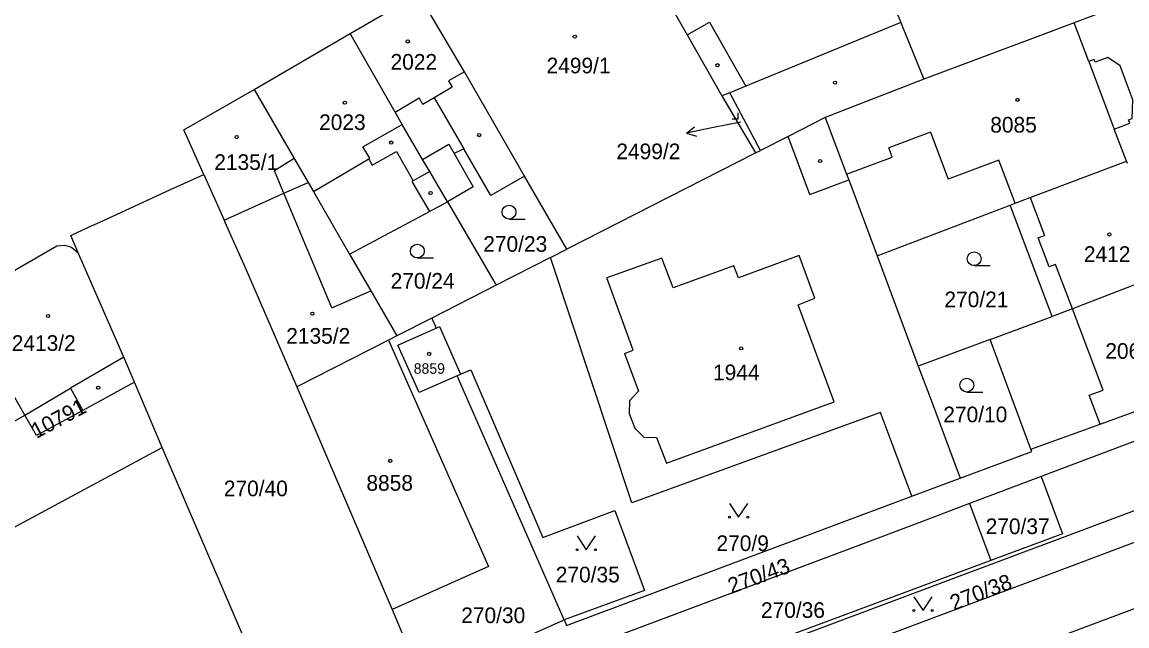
# Model space of a CAD drawing. Extents: x -564952 to -564307, y -1202373 to -1201847.
# Drawn here: x -564730.1 to -564610.1, y -1202266.1 to -1202200.5 of the extents above; entities that cross this region are included whole.
import ezdxf

# ---------------------------------------------------------------- set-up
doc = ezdxf.new("R2010")
doc.units = 0
for name, color, linetype in [('Hranice parcel', 7, 'Continuous'), ('Parcelní čísla', 7, 'Continuous'), ('Pop  PČ popisy', 7, 'Continuous'), ('Vnitřní kresba', 7, 'Continuous'), ('Značky budov', 7, 'Continuous'), ('Značky kultur', 7, 'Continuous')]:
    doc.layers.add(name, color=color, linetype=linetype)

msp = doc.modelspace()

# ---------------------------------------------------------------- linework, layer by layer
at = {"layer": 'Hranice parcel'}
for p, q in [((-564694.52, -1202201.73), (-564687.07, -1202197.41)), ((-564704.95, -1202207.82), (-564694.52, -1202201.73)), ((-564634.56, -1202200.83), (-564632.17, -1202206.71)), ((-564632.17, -1202206.71), (-564642.89, -1202210.85)), ((-564654.13, -1202208.52), (-564650.46, -1202214.71)), ((-564650.46, -1202214.71), (-564649.94, -1202214.44)), ((-564610.17, -1202215.61), (-564610.08, -1202215.84)), ((-564710.42, -1202217.06), (-564708.2, -1202222.02)), ((-564675.55, -1202217.24), (-564679.24, -1202219.35)), ((-564670.96, -1202225.17), (-564675.55, -1202217.24)), ((-564699.08, -1202217.91), (-564698.5, -1202218.91)), ((-564683.93, -1202220.03), (-564678.63, -1202229.08)), ((-564637.27, -1202225.88), (-564622.79, -1202220.37)), ((-564618.23, -1202232.47), (-564622.79, -1202220.37)), ((-564736.94, -1202230.91), (-564726.37, -1202224.82)), ((-564719.11, -1202236.91), (-564724.04, -1202225.55)), ((-564672.74, -1202226.07), (-564670.96, -1202225.17)), ((-564637.27, -1202225.88), (-564632.79, -1202237.88)), ((-564672.74, -1202226.07), (-564678.63, -1202229.08)), ((-564663.91, -1202252.75), (-564672.74, -1202226.07)), ((-564605.51, -1202227.59), (-564616.02, -1202231.64)), ((-564678.63, -1202229.08), (-564685.64, -1202232.65)), ((-564616.02, -1202231.64), (-564618.23, -1202232.47)), ((-564685.64, -1202232.65), (-564689.43, -1202234.59)), ((-564685.64, -1202232.65), (-564685.16, -1202233.75)), ((-564624.99, -1202234.98), (-564618.23, -1202232.47)), ((-564690.34, -1202235.06), (-564700.3, -1202240.13)), ((-564689.43, -1202234.59), (-564690.34, -1202235.06)), ((-564624.99, -1202234.98), (-564632.79, -1202237.88)), ((-564620.55, -1202246.92), (-564624.99, -1202234.98)), ((-564717.93, -1202239.63), (-564719.11, -1202236.91)), ((-564682.89, -1202238.94), (-564682.51, -1202238.77)), ((-564671.27, -1202265.46), (-564682.89, -1202238.94)), ((-564682.51, -1202238.77), (-564681.39, -1202238.28)), ((-564717.93, -1202239.63), (-564723.55, -1202242.69)), ((-564714.94, -1202246.71), (-564717.93, -1202239.63)), ((-564700.3, -1202240.13), (-564689.96, -1202264.32)), ((-564701.99, -1202276.83), (-564714.94, -1202246.71)), ((-564619.44, -1202249.88), (-564627.21, -1202252.81)), ((-564633.48, -1202252), (-564628.23, -1202250.07)), ((-564627.21, -1202252.81), (-564624.9, -1202259)), ((-564689.96, -1202264.32), (-564686.57, -1202272.24)), ((-564686.57, -1202272.24), (-564671.27, -1202265.46))]:
    msp.add_line(p, q, dxfattribs=at)
for points in [[(-564661.56, -1202195.43), (-564657.9, -1202201.87), (-564654.13, -1202208.52)], [(-564636.4, -1202196.4), (-564634.68, -1202200.55), (-564634.56, -1202200.83)], [(-564675.55, -1202217.24), (-564682.1, -1202205.88), (-564687.07, -1202197.41)], [(-564612.57, -1202199.34), (-564613.95, -1202199.85), (-564615.87, -1202200.58)], [(-564615.87, -1202200.58), (-564619.79, -1202202.05), (-564632.17, -1202206.71)], [(-564610.17, -1202215.61), (-564611.5, -1202212.11), (-564609.8, -1202211.47), (-564609.94, -1202211.11), (-564609.57, -1202210.97), (-564609.47, -1202208.95), (-564610.87, -1202205.24), (-564612.19, -1202204.34), (-564613.57, -1202204.86), (-564613.68, -1202204.56), (-564614.27, -1202204.79), (-564615.87, -1202200.58)], [(-564683.93, -1202220.03), (-564685.85, -1202216.74), (-564686.63, -1202215.41), (-564688.86, -1202211.61), (-564689.62, -1202210.28), (-564694.52, -1202201.73)], [(-564710.42, -1202217.06), (-564712.59, -1202212.2), (-564704.95, -1202207.82)], [(-564704.95, -1202207.82), (-564700.59, -1202215.31), (-564699.08, -1202217.91)], [(-564649.94, -1202214.44), (-564653.27, -1202208.17), (-564654.13, -1202208.52)], [(-564642.89, -1202210.85), (-564646.92, -1202212.91), (-564649.94, -1202214.44)], [(-564642.89, -1202210.85), (-564640.58, -1202217.03), (-564640.35, -1202217.64), (-564637.27, -1202225.88)], [(-564679.24, -1202219.35), (-564682.17, -1202214.26), (-564683.22, -1202214.76), (-564681.13, -1202218.39), (-564683.93, -1202220.03)], [(-564650.46, -1202214.71), (-564650.58, -1202214.77), (-564670.96, -1202225.17)], [(-564622.79, -1202220.37), (-564622.27, -1202220.18), (-564620.63, -1202219.56), (-564610.17, -1202215.61)], [(-564722.92, -1202222.77), (-564721.39, -1202222.08), (-564714.02, -1202218.67), (-564710.42, -1202217.06)], [(-564708.2, -1202222.02), (-564701.71, -1202219.09), (-564699.08, -1202217.91)], [(-564698.5, -1202218.91), (-564696.19, -1202222.9), (-564694.56, -1202225.72)], [(-564694.56, -1202225.72), (-564685.87, -1202221.07), (-564683.93, -1202220.03)], [(-564708.2, -1202222.02), (-564708.11, -1202222.23), (-564705.92, -1202227.17), (-564700.3, -1202240.13)], [(-564724.04, -1202225.55), (-564724.33, -1202224.89), (-564724.85, -1202223.68), (-564722.92, -1202222.77)], [(-564726.37, -1202224.82), (-564725.55, -1202224.73), (-564724.77, -1202224.94), (-564724.04, -1202225.55)], [(-564694.56, -1202225.72), (-564692.27, -1202229.68), (-564689.43, -1202234.59)], [(-564729.85, -1202243.2), (-564731.7, -1202239.94), (-564736.94, -1202230.91)], [(-564682.89, -1202238.94), (-564687.02, -1202240.76), (-564689.31, -1202235.59), (-564685.16, -1202233.75)], [(-564685.16, -1202233.75), (-564684.8, -1202233.59), (-564682.51, -1202238.77)], [(-564690.34, -1202235.06), (-564679.47, -1202259.66), (-564689.96, -1202264.32)], [(-564747.41, -1202236.95), (-564743.07, -1202244.93), (-564742.44, -1202246.04), (-564740.58, -1202249.32), (-564729.85, -1202243.2)], [(-564632.79, -1202237.88), (-564631.62, -1202241.01), (-564628.23, -1202250.07)], [(-564681.39, -1202238.28), (-564673.57, -1202256.49), (-564665.76, -1202253.57)], [(-564729.85, -1202243.2), (-564724.87, -1202240.28), (-564723.55, -1202242.69)], [(-564674.67, -1202281.56), (-564675.74, -1202278.47), (-564616.27, -1202256.18), (-564571.23, -1202239.28), (-564570.11, -1202242.25), (-564615.95, -1202259.53), (-564674.67, -1202281.56)], [(-564620.55, -1202246.92), (-564613.03, -1202244.17), (-564600.95, -1202239.75)], [(-564723.55, -1202242.69), (-564728.58, -1202245.43), (-564729.85, -1202243.2)], [(-564599.92, -1202242.52), (-564610.43, -1202246.48), (-564619.44, -1202249.88)], [(-564633.48, -1202252), (-564636.88, -1202242.92), (-564663.91, -1202252.75)], [(-564773.2, -1202285.97), (-564765.4, -1202281.28), (-564766.99, -1202277.53), (-564767.95, -1202275.27), (-564714.94, -1202246.71)], [(-564628.23, -1202250.07), (-564620.46, -1202247.17), (-564620.55, -1202246.92)], [(-564680.5, -1202290.94), (-564640.35, -1202275.83), (-564627.88, -1202271.16), (-564596.35, -1202259.35), (-564567, -1202248.34)], [(-564619.44, -1202249.88), (-564617.13, -1202256.1), (-564624.9, -1202259)], [(-564671.27, -1202265.46), (-564671, -1202266.08), (-564633.48, -1202252)], [(-564627.21, -1202252.81), (-564632.44, -1202254.79), (-564639.36, -1202257.4), (-564669.79, -1202268.83)], [(-564665.76, -1202253.57), (-564662.52, -1202262.26), (-564671.27, -1202265.46)], [(-564624.9, -1202259), (-564630.14, -1202260.95), (-564667.2, -1202274.75)]]:
    msp.add_lwpolyline(points, dxfattribs=at)
at = {"layer": 'Pop  PČ popisy'}
for p, q in [((-564652.05, -1202211.35), (-564655.04, -1202211.96)), ((-564657.97, -1202212.58), (-564657.1, -1202211.89)), ((-564655.04, -1202211.96), (-564657.97, -1202212.58)), ((-564657.97, -1202212.58), (-564656.89, -1202212.87))]:
    msp.add_line(p, q, dxfattribs=at)
at = {"layer": 'Vnitřní kresba'}
for p, q in [((-564657.9, -1202201.87), (-564655.48, -1202200.5)), ((-564655.48, -1202200.5), (-564651.53, -1202207.46)), ((-564634.68, -1202200.55), (-564651.53, -1202207.46)), ((-564614.27, -1202204.79), (-564611.5, -1202212.11)), ((-564682.1, -1202205.88), (-564683.82, -1202206.89)), ((-564683.43, -1202207.57), (-564685.37, -1202208.71)), ((-564683.82, -1202206.89), (-564683.43, -1202207.57)), ((-564651.53, -1202207.46), (-564653.27, -1202208.17)), ((-564689.62, -1202210.28), (-564687.01, -1202208.74)), ((-564686.61, -1202209.43), (-564687.01, -1202208.74)), ((-564685.37, -1202208.71), (-564686.61, -1202209.43)), ((-564685.37, -1202208.71), (-564682.17, -1202214.26)), ((-564693.13, -1202214.06), (-564688.86, -1202211.61)), ((-564631.45, -1202212.44), (-564636, -1202214.14)), ((-564631.45, -1202212.44), (-564629.53, -1202217.57)), ((-564686.63, -1202215.41), (-564683.8, -1202213.75)), ((-564683.8, -1202213.75), (-564683.22, -1202214.76)), ((-564644.56, -1202219.22), (-564646.92, -1202212.91)), ((-564692.36, -1202215.27), (-564693.13, -1202214.06)), ((-564692.11, -1202216.05), (-564689.49, -1202214.55)), ((-564689.49, -1202214.55), (-564687.66, -1202217.73)), ((-564635.61, -1202215.17), (-564636, -1202214.14)), ((-564700.59, -1202215.31), (-564702.74, -1202216.65)), ((-564698.5, -1202218.91), (-564692.49, -1202215.35)), ((-564692.49, -1202215.35), (-564692.36, -1202215.27)), ((-564692.49, -1202215.35), (-564692.11, -1202216.05)), ((-564640.58, -1202217.03), (-564635.61, -1202215.17)), ((-564624.03, -1202215.5), (-564629.53, -1202217.57)), ((-564622.27, -1202220.18), (-564624.03, -1202215.5)), ((-564701.71, -1202219.09), (-564702.74, -1202216.65)), ((-564685.85, -1202216.74), (-564687.66, -1202217.73)), ((-564687.66, -1202217.73), (-564687.79, -1202217.8)), ((-564687.79, -1202217.8), (-564685.87, -1202221.07)), ((-564644.56, -1202219.22), (-564640.35, -1202217.64)), ((-564696.49, -1202231.54), (-564701.71, -1202219.09)), ((-564620.63, -1202219.56), (-564619.07, -1202223.69)), ((-564619.76, -1202223.95), (-564619.07, -1202223.69)), ((-564618.58, -1202227.08), (-564619.76, -1202223.95)), ((-564645.74, -1202225.86), (-564652.33, -1202228.28)), ((-564644.01, -1202230.5), (-564645.74, -1202225.86)), ((-564660.66, -1202226.14), (-564666.62, -1202228.3)), ((-564659.41, -1202229.37), (-564660.66, -1202226.14)), ((-564652.81, -1202226.97), (-564659.41, -1202229.37)), ((-564652.33, -1202228.28), (-564652.81, -1202226.97)), ((-564617.89, -1202226.82), (-564618.58, -1202227.08)), ((-564616.02, -1202231.64), (-564617.89, -1202226.82)), ((-564663.75, -1202236.14), (-564666.62, -1202228.3)), ((-564696.49, -1202231.54), (-564692.27, -1202229.68)), ((-564645.83, -1202231.2), (-564644.01, -1202230.5)), ((-564641.94, -1202241.75), (-564645.83, -1202231.2)), ((-564612.69, -1202240.48), (-564616.02, -1202231.64)), ((-564664.72, -1202236.49), (-564663.75, -1202236.14)), ((-564664.72, -1202236.49), (-564663.2, -1202240.59)), ((-564719.11, -1202236.91), (-564724.87, -1202240.28)), ((-564663.2, -1202240.59), (-564664.15, -1202241.65)), ((-564614.21, -1202241.05), (-564612.69, -1202240.48)), ((-564613.03, -1202244.17), (-564614.21, -1202241.05)), ((-564664.15, -1202241.65), (-564664.2, -1202243.02)), ((-564660.15, -1202248.44), (-564641.94, -1202241.75)), ((-564664.2, -1202243.02), (-564663.58, -1202244.62)), ((-564663.58, -1202244.62), (-564662.59, -1202245.6)), ((-564662.59, -1202245.6), (-564661.22, -1202245.62)), ((-564661.22, -1202245.62), (-564660.15, -1202248.44))]:
    msp.add_line(p, q, dxfattribs=at)
at = {"layer": 'Značky budov'}
for centre in [(-564670.11, -1202202.07), (-564688.25, -1202202.59), (-564654.6, -1202205.18), (-564641.83, -1202207.07), (-564695.08, -1202209.25), (-564622.01, -1202208.94), (-564680.49, -1202212.77), (-564706.83, -1202212.99), (-564690.05, -1202213.58), (-564643.45, -1202215.59), (-564685.77, -1202219.07), (-564612.03, -1202223.57), (-564727.33, -1202232.43), (-564698.61, -1202232.18), (-564685.93, -1202236.55), (-564652.03, -1202235.95), (-564721.87, -1202240.22), (-564690.15, -1202248.17)]:
    msp.add_circle(centre, 0.175, dxfattribs=at)
at = {"layer": 'Značky kultur'}
for p, q in [((-564653.01, -1202211.01), (-564652.34, -1202211.01)), ((-564652.34, -1202211.01), (-564652.34, -1202210.34)), ((-564677.25, -1202221.89), (-564675.5, -1202221.89)), ((-564687.21, -1202226.12), (-564685.46, -1202226.12)), ((-564626.72, -1202226.96), (-564624.97, -1202226.96)), ((-564627.52, -1202240.69), (-564625.77, -1202240.69))]:
    msp.add_line(p, q, dxfattribs=at)
for points in [[(-564653.31, -1202252.79), (-564652.31, -1202254.29), (-564651.31, -1202252.79)], [(-564669.86, -1202256.33), (-564668.86, -1202257.83), (-564667.86, -1202256.33)], [(-564633.27, -1202262.94), (-564632.27, -1202264.44), (-564631.27, -1202262.94)]]:
    msp.add_lwpolyline(points, dxfattribs=at)
for centre, radius in [((-564677.25, -1202221.14), 0.75), ((-564687.21, -1202225.37), 0.75), ((-564626.72, -1202226.21), 0.75), ((-564627.52, -1202239.94), 0.75), ((-564653.31, -1202254.29), 0.1), ((-564651.31, -1202254.29), 0.1), ((-564669.86, -1202257.83), 0.1), ((-564667.86, -1202257.83), 0.1), ((-564633.27, -1202264.44), 0.1), ((-564631.27, -1202264.44), 0.1)]:
    msp.add_circle(centre, radius, dxfattribs=at)

# ---------------------------------------------------------------- texts
at = {"layer": 'Parcelní čísla'}
for s, height, p in [('2022', 1.7, (-564690.12, -1202205.66)), ('2499/1', 1.7, (-564673.17, -1202206.06)), ('2023', 1.7, (-564697.88, -1202212.22)), ('8085', 1.7, (-564624.97, -1202212.5)), ('2499/2', 1.7, (-564665.59, -1202215.39)), ('2135/1', 1.7, (-564709.27, -1202216.56)), ('270/23', 1.7, (-564680.05, -1202225.45)), ('2412', 1.7, (-564614.8, -1202226.55)), ('270/24', 1.7, (-564690.11, -1202229.46)), ('270/21', 1.7, (-564629.95, -1202231.48)), ('2135/2', 1.7, (-564701.45, -1202235.44)), ('2413/2', 1.7, (-564731.27, -1202236.22)), ('2066/1', 1.7, (-564612.47, -1202237.08)), ('8859', 1.14, (-564687.6, -1202238.71)), ('1944', 1.7, (-564655.09, -1202239.41)), ('270/10', 1.7, (-564630.07, -1202243.98)), ('8858', 1.7, (-564692.74, -1202251.42)), ('270/40', 1.7, (-564708.23, -1202252.02)), ('270/37', 1.7, (-564625.47, -1202256.13)), ('270/9', 1.7, (-564654.71, -1202257.97)), ('270/35', 1.7, (-564672.17, -1202261.38)), ('270/30', 1.7, (-564682.44, -1202265.8)), ('270/36', 1.7, (-564649.88, -1202265.24))]:
    msp.add_text(s, height=height, dxfattribs=at).set_placement(p)
for s, rotation, p in [('10791', 28, (-564728.59, -1202245.8)), ('270/43', 20, (-564653.1, -1202262.64)), ('270/38', 21, (-564628.94, -1202264.48))]:
    msp.add_text(s, height=1.7, rotation=rotation, dxfattribs=at).set_placement(p)

doc.saveas('drawing.dxf')
